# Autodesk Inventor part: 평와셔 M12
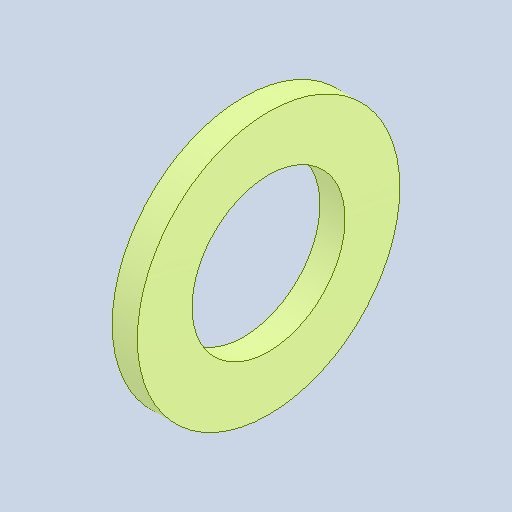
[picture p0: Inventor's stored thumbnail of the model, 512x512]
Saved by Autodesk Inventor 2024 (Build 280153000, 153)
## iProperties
Created: 2024-08
Part Number: 평와셔 M12
Material: 강철, 연강
Description: 평면 와셔
Document SubType Name: Modeling
Designer: user
Density: 7.85 g/cm^3
Appearance: 기본값
Author: jhkim
Sending System: Autodesk Inventor 2025
Preprocessor: ST-DEVELOPER v20
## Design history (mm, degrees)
feature "Solid1"
node "솔리드1"
